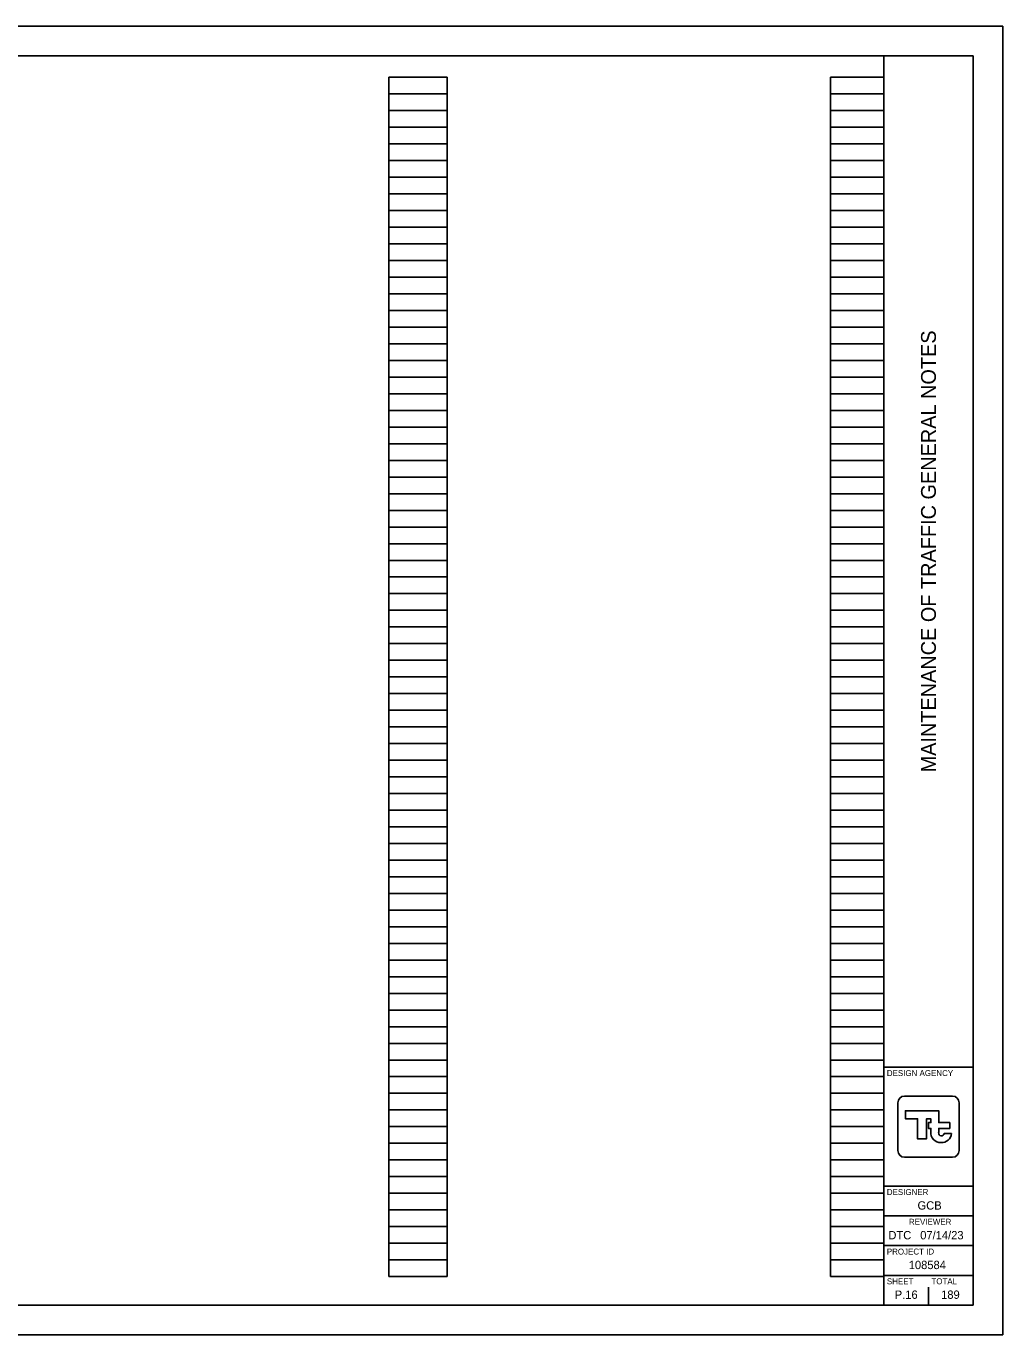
# Model space of a CAD drawing. Extents: x 0 to 34, y 0 to 22.
# Drawn here: x 17.58 to 34, y 0 to 22 of the extents above; entities that cross this region are included whole.
import ezdxf

# ---------------------------------------------------------------- set-up
doc = ezdxf.new("R2010")
doc.units = 0
for name, color, linetype in [('SH_Border', 7, 'Continuous'), ('SH_Cut_Line', 7, 'Continuous'), ('SH_Data', 7, 'Continuous')]:
    doc.layers.add(name, color=color, linetype=linetype)

msp = doc.modelspace()

# ---------------------------------------------------------------- linework, layer by layer
at = {"layer": 'SH_Border'}
for p, q in [((32, 0.5), (32, 21.5)), ((32, 4.5), (33.5, 4.5)), ((32, 2.5), (33.5, 2.5)), ((32, 2), (33.5, 2)), ((32, 1.5), (33.5, 1.5)), ((32, 1), (33.5, 1))]:
    msp.add_line(p, q, dxfattribs=at)
msp.add_lwpolyline([(1.5, 21.5), (33.5, 21.5), (33.5, 0.5), (1.5, 0.5)], close=True, dxfattribs=at)
at = {"layer": 'SH_Cut_Line'}
msp.add_lwpolyline([(0, 0), (34, 0), (34, 22), (0, 22)], close=True, dxfattribs=at)
at = {"layer": 'SH_Data'}
for p, q in [((23.68, 0.98), (23.68, 21.14)), ((23.68, 21.14), (24.66, 21.14)), ((24.66, 0.98), (24.66, 21.14)), ((31.1, 0.98), (31.1, 21.14)), ((31.1, 21.14), (32, 21.14)), ((32, 0.98), (32, 21.14)), ((23.68, 20.86), (24.66, 20.86)), ((31.1, 20.86), (32, 20.86)), ((23.68, 20.58), (24.66, 20.58)), ((31.1, 20.58), (32, 20.58)), ((23.68, 20.3), (24.66, 20.3)), ((31.1, 20.3), (32, 20.3)), ((23.68, 20.02), (24.66, 20.02)), ((31.1, 20.02), (32, 20.02)), ((23.68, 19.74), (24.66, 19.74)), ((31.1, 19.74), (32, 19.74)), ((23.68, 19.46), (24.66, 19.46)), ((31.1, 19.46), (32, 19.46)), ((23.68, 19.18), (24.66, 19.18)), ((31.1, 19.18), (32, 19.18)), ((23.68, 18.9), (24.66, 18.9)), ((31.1, 18.9), (32, 18.9)), ((23.68, 18.62), (24.66, 18.62)), ((31.1, 18.62), (32, 18.62)), ((23.68, 18.34), (24.66, 18.34)), ((31.1, 18.34), (32, 18.34)), ((23.68, 18.06), (24.66, 18.06)), ((31.1, 18.06), (32, 18.06)), ((23.68, 17.78), (24.66, 17.78)), ((31.1, 17.78), (32, 17.78)), ((23.68, 17.5), (24.66, 17.5)), ((31.1, 17.5), (32, 17.5)), ((23.68, 17.22), (24.66, 17.22)), ((31.1, 17.22), (32, 17.22)), ((23.68, 16.94), (24.66, 16.94)), ((31.1, 16.94), (32, 16.94)), ((23.68, 16.66), (24.66, 16.66)), ((31.1, 16.66), (32, 16.66)), ((23.68, 16.38), (24.66, 16.38)), ((31.1, 16.38), (32, 16.38)), ((23.68, 16.1), (24.66, 16.1)), ((31.1, 16.1), (32, 16.1)), ((23.68, 15.82), (24.66, 15.82)), ((31.1, 15.82), (32, 15.82)), ((23.68, 15.54), (24.66, 15.54)), ((31.1, 15.54), (32, 15.54)), ((23.68, 15.26), (24.66, 15.26)), ((31.1, 15.26), (32, 15.26)), ((23.68, 14.98), (24.66, 14.98)), ((31.1, 14.98), (32, 14.98)), ((23.68, 14.7), (24.66, 14.7)), ((31.1, 14.7), (32, 14.7)), ((23.68, 14.42), (24.66, 14.42)), ((31.1, 14.42), (32, 14.42)), ((23.68, 14.14), (24.66, 14.14)), ((31.1, 14.14), (32, 14.14)), ((23.68, 13.86), (24.66, 13.86)), ((31.1, 13.86), (32, 13.86)), ((23.68, 13.58), (24.66, 13.58)), ((31.1, 13.58), (32, 13.58)), ((23.68, 13.3), (24.66, 13.3)), ((31.1, 13.3), (32, 13.3)), ((23.68, 13.02), (24.66, 13.02)), ((31.1, 13.02), (32, 13.02)), ((23.68, 12.74), (24.66, 12.74)), ((31.1, 12.74), (32, 12.74)), ((23.68, 12.46), (24.66, 12.46)), ((31.1, 12.46), (32, 12.46)), ((23.68, 12.18), (24.66, 12.18)), ((31.1, 12.18), (32, 12.18)), ((23.68, 11.9), (24.66, 11.9)), ((31.1, 11.9), (32, 11.9)), ((23.68, 11.62), (24.66, 11.62)), ((31.1, 11.62), (32, 11.62)), ((23.68, 11.34), (24.66, 11.34)), ((31.1, 11.34), (32, 11.34)), ((23.68, 11.06), (24.66, 11.06)), ((31.1, 11.06), (32, 11.06)), ((23.68, 10.78), (24.66, 10.78)), ((31.1, 10.78), (32, 10.78)), ((23.68, 10.5), (24.66, 10.5)), ((31.1, 10.5), (32, 10.5)), ((23.68, 10.22), (24.66, 10.22)), ((31.1, 10.22), (32, 10.22)), ((23.68, 9.94), (24.66, 9.94)), ((31.1, 9.94), (32, 9.94)), ((23.68, 9.66), (24.66, 9.66)), ((31.1, 9.66), (32, 9.66)), ((23.68, 9.38), (24.66, 9.38)), ((31.1, 9.38), (32, 9.38)), ((23.68, 9.1), (24.66, 9.1)), ((31.1, 9.1), (32, 9.1)), ((23.68, 8.82), (24.66, 8.82)), ((31.1, 8.82), (32, 8.82)), ((23.68, 8.54), (24.66, 8.54)), ((31.1, 8.54), (32, 8.54)), ((23.68, 8.26), (24.66, 8.26)), ((31.1, 8.26), (32, 8.26)), ((23.68, 7.98), (24.66, 7.98)), ((31.1, 7.98), (32, 7.98)), ((23.68, 7.7), (24.66, 7.7)), ((31.1, 7.7), (32, 7.7)), ((23.68, 7.42), (24.66, 7.42)), ((31.1, 7.42), (32, 7.42)), ((23.68, 7.14), (24.66, 7.14)), ((31.1, 7.14), (32, 7.14)), ((23.68, 6.86), (24.66, 6.86)), ((31.1, 6.86), (32, 6.86)), ((23.68, 6.58), (24.66, 6.58)), ((31.1, 6.58), (32, 6.58)), ((23.68, 6.3), (24.66, 6.3)), ((31.1, 6.3), (32, 6.3)), ((23.68, 6.02), (24.66, 6.02)), ((31.1, 6.02), (32, 6.02)), ((23.68, 5.74), (24.66, 5.74)), ((31.1, 5.74), (32, 5.74)), ((23.68, 5.46), (24.66, 5.46)), ((31.1, 5.46), (32, 5.46)), ((23.68, 5.18), (24.66, 5.18)), ((31.1, 5.18), (32, 5.18)), ((23.68, 4.9), (24.66, 4.9)), ((31.1, 4.9), (32, 4.9)), ((23.68, 4.62), (24.66, 4.62)), ((31.1, 4.62), (32, 4.62)), ((23.68, 4.34), (24.66, 4.34)), ((31.1, 4.34), (32, 4.34)), ((23.68, 4.06), (24.66, 4.06)), ((31.1, 4.06), (32, 4.06)), ((23.68, 3.78), (24.66, 3.78)), ((31.1, 3.78), (32, 3.78)), ((23.68, 3.5), (24.66, 3.5)), ((31.1, 3.5), (32, 3.5)), ((32.75, 3.5), (32.75, 3.5)), ((32.791, 3.415), (32.791, 3.415)), ((33.136, 3.385), (33.015, 3.385)), ((23.68, 3.22), (24.66, 3.22)), ((31.1, 3.22), (32, 3.22)), ((23.68, 2.94), (24.66, 2.94)), ((31.1, 2.94), (32, 2.94)), ((23.68, 2.66), (24.66, 2.66)), ((31.1, 2.66), (32, 2.66)), ((23.68, 2.38), (24.66, 2.38)), ((31.1, 2.38), (32, 2.38)), ((23.68, 2.1), (24.66, 2.1)), ((31.1, 2.1), (32, 2.1)), ((23.68, 1.82), (24.66, 1.82)), ((31.1, 1.82), (32, 1.82)), ((23.68, 1.54), (24.66, 1.54)), ((31.1, 1.54), (32, 1.54)), ((23.68, 1.26), (24.66, 1.26)), ((31.1, 1.26), (32, 1.26)), ((23.68, 0.98), (24.66, 0.98)), ((31.1, 0.98), (32, 0.98)), ((32.375, 0.675), (32.375, 0.675)), ((32.75, 0.5), (32.75, 0.8))]:
    msp.add_line(p, q, dxfattribs=at)
for points in [[(32.348, 4.014), (33.152, 4.014)], [(32.236, 3.099), (32.236, 3.901)], [(32.922, 3.399), (32.922, 3.47), (33.107, 3.47), (33.107, 3.568), (32.922, 3.568), (32.922, 3.768), (32.361, 3.768), (32.361, 3.632), (32.566, 3.632), (32.566, 3.294), (32.715, 3.294), (32.715, 3.63), (32.79, 3.63), (32.79, 3.568), (32.748, 3.568), (32.748, 3.47), (32.79, 3.47), (32.79, 3.415), (32.791, 3.415)], [(33.264, 3.901), (33.264, 3.099)], [(33.152, 2.986), (32.348, 2.986)]]:
    msp.add_lwpolyline(points, dxfattribs=at)
for centre, radius, start, end in [((32.348, 3.901), 0.113, 90, 180), ((33.152, 3.901), 0.113, 360, 90), ((32.949, 3.392), 0.16, 171.8856, 274.8323), ((32.968, 3.392), 0.0473, 171.8856, 350.9243), ((32.976, 3.392), 0.16, 265.1677, 357.3201), ((32.348, 3.099), 0.113, 180, 270), ((33.152, 3.099), 0.113, 270, 360)]:
    msp.add_arc(centre, radius, start, end, dxfattribs=at)

# ---------------------------------------------------------------- texts
msp.add_text('MAINTENANCE OF TRAFFIC GENERAL NOTES', height=0.25, rotation=90, dxfattribs=at).set_placement((32.875, 9.455))
for s, height, p in [('DESIGN AGENCY', 0.1, (32.05, 4.35)), ('DESIGNER', 0.1, (32.05, 2.35)), ('GCB', 0.14, (32.566, 2.105)), ('REVIEWER', 0.1, (32.422, 1.85)), ('DTC', 0.14, (32.076, 1.605)), ('07/14/23', 0.14, (32.611, 1.605)), ('PROJECT ID', 0.1, (32.05, 1.35)), ('108584', 0.14, (32.418, 1.105)), ('SHEET', 0.1, (32.05, 0.85)), ('TOTAL', 0.1, (32.8, 0.85)), ('P.16', 0.14, (32.183, 0.605)), ('189', 0.14, (32.963, 0.605))]:
    msp.add_text(s, height=height, dxfattribs=at).set_placement(p)

doc.saveas('drawing.dxf')
